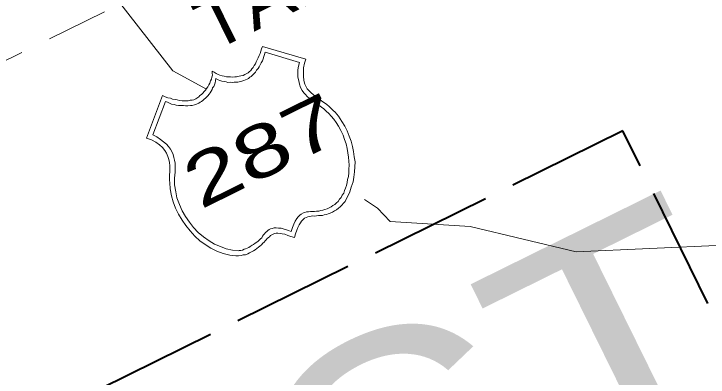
# Model space of a CAD drawing. Extents: x 2356606 to 2371222, y 6973096 to 6982644.
# Drawn here: x 2370773.7 to 2370841.6, y 6980470.1 to 6980505.6 of the extents above; entities that cross this region are included whole.
import ezdxf

# ---------------------------------------------------------------- set-up
doc = ezdxf.new("R2010")
doc.units = 0
doc.header["$LTSCALE"] = 2
doc.linetypes.add('LONG_DASHED', pattern=[7.5, 6, -1.5])
doc.linetypes.add('MEDIUM_DASHED', pattern=[4.5, 3, -1.5])
doc.layers.add('62', color=7, linetype='Continuous', lineweight=13)
doc.layers.add('63', color=7, linetype='Continuous', lineweight=13)

msp = doc.modelspace()

# ---------------------------------------------------------------- linework, layer by layer
at = {"layer": '62', "linetype": 'MEDIUM_DASHED'}
msp.add_line((2371056.951, 6980641.227), (2370654.977, 6980442.841), dxfattribs=at)
at = {"layer": '62'}
for p, q in [((2370789.238, 6980500.02), (2370792.529, 6980498.232)), ((2370809.285, 6980486.6), (2370807.99, 6980487.443))]:
    msp.add_line(p, q, dxfattribs=at)
for points in [[(2370702.875, 6980572.249), (2370710.55, 6980569.261), (2370722.237, 6980561.754), (2370733.315, 6980552.568), (2370741.816, 6980540.43), (2370746.099, 6980533.281), (2370753.777, 6980526.006), (2370764.976, 6980522.023), (2370774.536, 6980517.706), (2370781.469, 6980510.013), (2370789.238, 6980500.02)], [(2370786.658, 6980493.452), (2370788.25, 6980497.601), (2370788.5, 6980497.497), (2370788.753, 6980497.396), (2370789.005, 6980497.345), (2370789.223, 6980497.253), (2370789.465, 6980497.224), (2370789.687, 6980497.18), (2370789.908, 6980497.139), (2370790.149, 6980497.107), (2370790.342, 6980497.077), (2370790.553, 6980497.106), (2370790.751, 6980497.103), (2370790.953, 6980497.153), (2370791.145, 6980497.172), (2370791.306, 6980497.202), (2370791.509, 6980497.302), (2370791.68, 6980497.412), (2370791.791, 6980497.491), (2370791.904, 6980497.622), (2370792.056, 6980497.721), (2370792.196, 6980497.84), (2370792.315, 6980498.001), (2370792.429, 6980498.132), (2370792.55, 6980498.293), (2370792.672, 6980498.453), (2370792.754, 6980498.644), (2370792.865, 6980498.824), (2370792.938, 6980499.034), (2370793.029, 6980499.206), (2370793.058, 6980499.396), (2370793.113, 6980499.597), (2370793.091, 6980499.79), (2370793.11, 6980500), (2370793.292, 6980499.889), (2370793.473, 6980499.775), (2370793.674, 6980499.676), (2370793.854, 6980499.613), (2370794.076, 6980499.522), (2370794.285, 6980499.5), (2370794.489, 6980499.449), (2370794.701, 6980499.429), (2370794.901, 6980499.427), (2370795.093, 6980499.395), (2370795.323, 6980499.435), (2370795.493, 6980499.444), (2370795.737, 6980499.514), (2370795.907, 6980499.521), (2370796.129, 6980499.583), (2370796.29, 6980499.662), (2370796.433, 6980499.73), (2370796.614, 6980499.82), (2370796.703, 6980499.941), (2370796.867, 6980500.072), (2370796.988, 6980500.232), (2370797.099, 6980500.36), (2370797.19, 6980500.532), (2370797.322, 6980500.722), (2370797.413, 6980500.893), (2370797.515, 6980501.094), (2370797.599, 6980501.285), (2370797.709, 6980501.515), (2370797.78, 6980501.727), (2370797.872, 6980501.948), (2370797.932, 6980502.179), (2370798.016, 6980502.421), (2370802.275, 6980501.16), (2370802.142, 6980500.766), (2370802.029, 6980500.335), (2370802.017, 6980499.904), (2370802.045, 6980499.493), (2370802.074, 6980499.079), (2370802.174, 6980498.727), (2370802.302, 6980498.463), (2370802.391, 6980498.282), (2370802.5, 6980498.16), (2370802.652, 6980498.007), (2370802.792, 6980497.877), (2370802.972, 6980497.714), (2370803.171, 6980497.56), (2370803.372, 6980497.411), (2370803.605, 6980497.25), (2370803.843, 6980497.067), (2370804.075, 6980496.903), (2370804.305, 6980496.741), (2370804.536, 6980496.53), (2370804.746, 6980496.357), (2370804.948, 6980496.156), (2370805.136, 6980495.973), (2370805.307, 6980495.78), (2370805.456, 6980495.579), (2370805.776, 6980495.085), (2370806.086, 6980494.61), (2370806.315, 6980494.145), (2370806.494, 6980493.629), (2370806.684, 6980493.144), (2370806.83, 6980492.641), (2370806.929, 6980492.138), (2370807.006, 6980491.624), (2370807.074, 6980491.129), (2370807.07, 6980490.626)], [(2370806.352, 6980489.394), (2370806.423, 6980489.705), (2370806.454, 6980490.045), (2370806.478, 6980490.407), (2370806.491, 6980490.793), (2370806.471, 6980491.185), (2370806.442, 6980491.596), (2370806.383, 6980492.019), (2370806.305, 6980492.434), (2370806.207, 6980492.886), (2370806.05, 6980493.312), (2370805.91, 6980493.745), (2370805.692, 6980494.188), (2370805.461, 6980494.602), (2370805.222, 6980494.985), (2370805.012, 6980495.308), (2370804.751, 6980495.583), (2370804.522, 6980495.845), (2370804.262, 6980496.067), (2370804.02, 6980496.3), (2370803.781, 6980496.483), (2370803.52, 6980496.655), (2370803.258, 6980496.827), (2370803.031, 6980496.99), (2370802.818, 6980497.163), (2370802.607, 6980497.334), (2370802.396, 6980497.508), (2370802.226, 6980497.699), (2370802.067, 6980497.871), (2370801.907, 6980498.093), (2370801.738, 6980498.384), (2370801.649, 6980498.719), (2370801.561, 6980499.052), (2370801.49, 6980499.393), (2370801.464, 6980499.754), (2370801.487, 6980500.119), (2370801.555, 6980500.481), (2370801.63, 6980500.841), (2370798.273, 6980501.845), (2370798.204, 6980501.633), (2370798.149, 6980501.432), (2370798.089, 6980501.201), (2370798.009, 6980501.01), (2370797.907, 6980500.809), (2370797.806, 6980500.609), (2370797.693, 6980500.43), (2370797.583, 6980500.248), (2370797.441, 6980500.078), (2370797.327, 6980499.897), (2370797.176, 6980499.747), (2370797.043, 6980499.606), (2370796.903, 6980499.487), (2370796.772, 6980499.396), (2370796.652, 6980499.286), (2370796.511, 6980499.218), (2370796.368, 6980499.147), (2370796.197, 6980499.088), (2370796.005, 6980499.02), (2370795.855, 6980498.968), (2370795.623, 6980498.931), (2370795.452, 6980498.921), (2370795.262, 6980498.903), (2370795.039, 6980498.893), (2370794.86, 6980498.904), (2370794.637, 6980498.894), (2370794.465, 6980498.936), (2370794.275, 6980498.969), (2370794.052, 6980499.008), (2370793.861, 6980499.09), (2370793.681, 6980499.152), (2370793.47, 6980499.275), (2370793.429, 6980499.051), (2370793.378, 6980498.852), (2370793.316, 6980498.67), (2370793.246, 6980498.51), (2370793.144, 6980498.359), (2370793.092, 6980498.211), (2370792.984, 6980498.028), (2370792.909, 6980497.868), (2370792.79, 6980497.756), (2370792.669, 6980497.596), (2370792.566, 6980497.497), (2370792.435, 6980497.356), (2370792.302, 6980497.267), (2370792.193, 6980497.136), (2370792.041, 6980497.038), (2370791.91, 6980496.946), (2370791.78, 6980496.857), (2370791.577, 6980496.757), (2370791.376, 6980496.709), (2370791.155, 6980496.65), (2370790.961, 6980496.631), (2370790.72, 6980496.61), (2370790.477, 6980496.59), (2370790.289, 6980496.625), (2370790.037, 6980496.624), (2370789.805, 6980496.637), (2370789.582, 6980496.677), (2370789.374, 6980496.748), (2370789.131, 6980496.779), (2370788.911, 6980496.872)], [(2370788.538, 6980497.014), (2370787.282, 6980493.759), (2370787.683, 6980493.557), (2370788.055, 6980493.314), (2370788.346, 6980493.081), (2370788.626, 6980492.867), (2370788.826, 6980492.615), (2370789.027, 6980492.362), (2370789.165, 6980492.131), (2370789.276, 6980491.858), (2370789.344, 6980491.565), (2370789.424, 6980491.304), (2370789.473, 6980491.003), (2370789.472, 6980490.701), (2370789.479, 6980490.428), (2370789.479, 6980490.127), (2370789.446, 6980489.836), (2370789.425, 6980489.523), (2370789.421, 6980488.87), (2370789.527, 6980488.195), (2370789.646, 6980487.6), (2370789.885, 6980486.967), (2370790.164, 6980486.349), (2370790.472, 6980485.773), (2370790.873, 6980485.215), (2370791.273, 6980484.712), (2370791.742, 6980484.217), (2370792.254, 6980483.789), (2370792.796, 6980483.406), (2370793.334, 6980483.07), (2370793.899, 6980482.847), (2370794.48, 6980482.632), (2370795.075, 6980482.498), (2370795.639, 6980482.426), (2370795.75, 6980482.454), (2370795.902, 6980482.453), (2370796.051, 6980482.504), (2370796.213, 6980482.582), (2370796.345, 6980482.623), (2370796.517, 6980482.681), (2370796.678, 6980482.761), (2370796.827, 6980482.861), (2370797, 6980482.972), (2370797.142, 6980483.041), (2370797.304, 6980483.17), (2370797.455, 6980483.271), (2370797.586, 6980483.362), (2370797.718, 6980483.5), (2370797.838, 6980483.61), (2370797.942, 6980483.712), (2370798.02, 6980483.851), (2370798.133, 6980483.98), (2370798.205, 6980484.092), (2370798.314, 6980484.223), (2370798.437, 6980484.331), (2370798.546, 6980484.412), (2370798.678, 6980484.503), (2370798.82, 6980484.572), (2370798.972, 6980484.621), (2370799.172, 6980484.672), (2370799.364, 6980484.69), (2370799.585, 6980484.649), (2370799.836, 6980484.646), (2370800.138, 6980484.544), (2370800.48, 6980484.462), (2370800.832, 6980484.309), (2370800.954, 6980484.721), (2370801.097, 6980485.042), (2370801.23, 6980485.334), (2370801.381, 6980485.583), (2370801.523, 6980485.756), (2370801.674, 6980485.906), (2370801.816, 6980486.026), (2370802.017, 6980486.125), (2370802.169, 6980486.173), (2370802.321, 6980486.226), (2370802.532, 6980486.252), (2370802.722, 6980486.272), (2370802.894, 6980486.282), (2370803.097, 6980486.281), (2370803.307, 6980486.309), (2370803.528, 6980486.317), (2370803.73, 6980486.367), (2370803.941, 6980486.397), (2370804.132, 6980486.466), (2370804.345, 6980486.546), (2370804.536, 6980486.614), (2370804.727, 6980486.735), (2370804.9, 6980486.845), (2370805.09, 6980486.965), (2370805.263, 6980487.125), (2370805.425, 6980487.254), (2370805.566, 6980487.475), (2370805.709, 6980487.646), (2370805.83, 6980487.857), (2370805.971, 6980488.076), (2370806.053, 6980488.318), (2370806.157, 6980488.568), (2370806.239, 6980488.809), (2370806.29, 6980489.112), (2370806.352, 6980489.394)], [(2370788.911, 6980496.872), (2370788.719, 6980496.954), (2370788.538, 6980497.014)], [(2370787.581, 6980493.055), (2370787.17, 6980493.279), (2370786.658, 6980493.452)], [(2370807.07, 6980490.626), (2370807.039, 6980490.134), (2370806.956, 6980489.642), (2370806.892, 6980489.158), (2370806.71, 6980488.667), (2370806.567, 6980488.194), (2370806.351, 6980487.713), (2370806.22, 6980487.472), (2370806.097, 6980487.261), (2370805.936, 6980487.081), (2370805.776, 6980486.9), (2370805.634, 6980486.73), (2370805.452, 6980486.589), (2370805.249, 6980486.441), (2370805.08, 6980486.331), (2370804.866, 6980486.199), (2370804.653, 6980486.121), (2370804.461, 6980486.052), (2370804.29, 6980485.993), (2370804.061, 6980485.954), (2370803.888, 6980485.895), (2370803.695, 6980485.874), (2370803.496, 6980485.876), (2370803.314, 6980485.837), (2370803.123, 6980485.818), (2370802.961, 6980485.839), (2370802.77, 6980485.819), (2370802.641, 6980485.782), (2370802.459, 6980485.74), (2370802.285, 6980485.68), (2370802.147, 6980485.612), (2370802.004, 6980485.492), (2370801.853, 6980485.341), (2370801.743, 6980485.162), (2370801.609, 6980484.971), (2370801.488, 6980484.711), (2370801.366, 6980484.447), (2370801.262, 6980484.098), (2370801.151, 6980483.716), (2370800.788, 6980483.838), (2370800.488, 6980483.94), (2370800.206, 6980484.051), (2370799.944, 6980484.074), (2370799.741, 6980484.124), (2370799.532, 6980484.147), (2370799.36, 6980484.137), (2370799.2, 6980484.105), (2370799.069, 6980484.068), (2370798.928, 6980483.997), (2370798.817, 6980483.919), (2370798.695, 6980483.807), (2370798.605, 6980483.738), (2370798.484, 6980483.63), (2370798.371, 6980483.498), (2370798.271, 6980483.397), (2370798.178, 6980483.278), (2370798.057, 6980483.167), (2370797.926, 6980483.026), (2370797.776, 6980482.878), (2370797.624, 6980482.778), (2370797.463, 6980482.648), (2370797.298, 6980482.517), (2370797.147, 6980482.417), (2370796.948, 6980482.318), (2370796.765, 6980482.228), (2370796.584, 6980482.139), (2370796.35, 6980482.049), (2370796.141, 6980482.02), (2370795.918, 6980481.96), (2370795.673, 6980481.941), (2370795.424, 6980481.941), (2370794.81, 6980482.017), (2370794.177, 6980482.18), (2370793.545, 6980482.394), (2370792.973, 6980482.69), (2370792.401, 6980483.036), (2370791.888, 6980483.41), (2370791.411, 6980483.875), (2370790.939, 6980484.37), (2370790.508, 6980484.887), (2370790.148, 6980485.413), (2370789.809, 6980485.997), (2370789.519, 6980486.583), (2370789.281, 6980487.219), (2370789.113, 6980487.814), (2370788.986, 6980488.478), (2370788.941, 6980489.083), (2370788.92, 6980489.325), (2370788.921, 6980489.576), (2370788.934, 6980489.858), (2370788.945, 6980490.138), (2370788.946, 6980490.442), (2370788.95, 6980490.743), (2370788.918, 6980491.055), (2370788.85, 6980491.348), (2370788.773, 6980491.661), (2370788.622, 6980491.962), (2370788.463, 6980492.234), (2370788.223, 6980492.518), (2370787.94, 6980492.78), (2370787.581, 6980493.055)], [(2370809.285, 6980486.6), (2370810.526, 6980485.306), (2370818.332, 6980484.791), (2370828.717, 6980482.314), (2370843.121, 6980482.975), (2370855.891, 6980481.246), (2370863.629, 6980480.974)]]:
    msp.add_lwpolyline(points, dxfattribs=at)
at = {"layer": '62', "linetype": 'LONG_DASHED', "lineweight": 40}
msp.add_lwpolyline([(2370677.388, 6980417.215), (2370705.629, 6980359.988), (2370861.529, 6980436.93), (2370833.286, 6980494.155), (2370677.105, 6980417.075)], dxfattribs=at)
at = {"layer": '63', "linetype": 'MEDIUM_DASHED'}
msp.add_line((2371056.951, 6980641.227), (2370654.977, 6980442.841), dxfattribs=at)
at = {"layer": '63'}
for p, q in [((2370789.238, 6980500.02), (2370792.529, 6980498.232)), ((2370809.285, 6980486.6), (2370807.99, 6980487.443))]:
    msp.add_line(p, q, dxfattribs=at)
for points in [[(2370702.875, 6980572.249), (2370710.55, 6980569.261), (2370722.237, 6980561.754), (2370733.315, 6980552.568), (2370741.816, 6980540.43), (2370746.099, 6980533.281), (2370753.777, 6980526.006), (2370764.976, 6980522.023), (2370774.536, 6980517.706), (2370781.469, 6980510.013), (2370789.238, 6980500.02)], [(2370786.658, 6980493.452), (2370788.25, 6980497.601), (2370788.5, 6980497.497), (2370788.753, 6980497.396), (2370789.005, 6980497.345), (2370789.223, 6980497.253), (2370789.465, 6980497.224), (2370789.687, 6980497.18), (2370789.908, 6980497.139), (2370790.149, 6980497.107), (2370790.342, 6980497.077), (2370790.553, 6980497.106), (2370790.751, 6980497.103), (2370790.953, 6980497.153), (2370791.145, 6980497.172), (2370791.306, 6980497.202), (2370791.509, 6980497.302), (2370791.68, 6980497.412), (2370791.791, 6980497.491), (2370791.904, 6980497.622), (2370792.056, 6980497.721), (2370792.196, 6980497.84), (2370792.315, 6980498.001), (2370792.429, 6980498.132), (2370792.55, 6980498.293), (2370792.672, 6980498.453), (2370792.754, 6980498.644), (2370792.865, 6980498.824), (2370792.938, 6980499.034), (2370793.029, 6980499.206), (2370793.058, 6980499.396), (2370793.113, 6980499.597), (2370793.091, 6980499.79), (2370793.11, 6980500), (2370793.292, 6980499.889), (2370793.473, 6980499.775), (2370793.674, 6980499.676), (2370793.854, 6980499.613), (2370794.076, 6980499.522), (2370794.285, 6980499.5), (2370794.489, 6980499.449), (2370794.701, 6980499.429), (2370794.901, 6980499.427), (2370795.093, 6980499.395), (2370795.323, 6980499.435), (2370795.493, 6980499.444), (2370795.737, 6980499.514), (2370795.907, 6980499.521), (2370796.129, 6980499.583), (2370796.29, 6980499.662), (2370796.433, 6980499.73), (2370796.614, 6980499.82), (2370796.703, 6980499.941), (2370796.867, 6980500.072), (2370796.988, 6980500.232), (2370797.099, 6980500.36), (2370797.19, 6980500.532), (2370797.322, 6980500.722), (2370797.413, 6980500.893), (2370797.515, 6980501.094), (2370797.599, 6980501.285), (2370797.709, 6980501.515), (2370797.78, 6980501.727), (2370797.872, 6980501.948), (2370797.932, 6980502.179), (2370798.016, 6980502.421), (2370802.275, 6980501.16), (2370802.142, 6980500.766), (2370802.029, 6980500.335), (2370802.017, 6980499.904), (2370802.045, 6980499.493), (2370802.074, 6980499.079), (2370802.174, 6980498.727), (2370802.302, 6980498.463), (2370802.391, 6980498.282), (2370802.5, 6980498.16), (2370802.652, 6980498.007), (2370802.792, 6980497.877), (2370802.972, 6980497.714), (2370803.171, 6980497.56), (2370803.372, 6980497.411), (2370803.605, 6980497.25), (2370803.843, 6980497.067), (2370804.075, 6980496.903), (2370804.305, 6980496.741), (2370804.536, 6980496.53), (2370804.746, 6980496.357), (2370804.948, 6980496.156), (2370805.136, 6980495.973), (2370805.307, 6980495.78), (2370805.456, 6980495.579), (2370805.776, 6980495.085), (2370806.086, 6980494.61), (2370806.315, 6980494.145), (2370806.494, 6980493.629), (2370806.684, 6980493.144), (2370806.83, 6980492.641), (2370806.929, 6980492.138), (2370807.006, 6980491.624), (2370807.074, 6980491.129), (2370807.07, 6980490.626)], [(2370806.352, 6980489.394), (2370806.423, 6980489.705), (2370806.454, 6980490.045), (2370806.478, 6980490.407), (2370806.491, 6980490.793), (2370806.471, 6980491.185), (2370806.442, 6980491.596), (2370806.383, 6980492.019), (2370806.305, 6980492.434), (2370806.207, 6980492.886), (2370806.05, 6980493.312), (2370805.91, 6980493.745), (2370805.692, 6980494.188), (2370805.461, 6980494.602), (2370805.222, 6980494.985), (2370805.012, 6980495.308), (2370804.751, 6980495.583), (2370804.522, 6980495.845), (2370804.262, 6980496.067), (2370804.02, 6980496.3), (2370803.781, 6980496.483), (2370803.52, 6980496.655), (2370803.258, 6980496.827), (2370803.031, 6980496.99), (2370802.818, 6980497.163), (2370802.607, 6980497.334), (2370802.396, 6980497.508), (2370802.226, 6980497.699), (2370802.067, 6980497.871), (2370801.907, 6980498.093), (2370801.738, 6980498.384), (2370801.649, 6980498.719), (2370801.561, 6980499.052), (2370801.49, 6980499.393), (2370801.464, 6980499.754), (2370801.487, 6980500.119), (2370801.555, 6980500.481), (2370801.63, 6980500.841), (2370798.273, 6980501.845), (2370798.204, 6980501.633), (2370798.149, 6980501.432), (2370798.089, 6980501.201), (2370798.009, 6980501.01), (2370797.907, 6980500.809), (2370797.806, 6980500.609), (2370797.693, 6980500.43), (2370797.583, 6980500.248), (2370797.441, 6980500.078), (2370797.327, 6980499.897), (2370797.176, 6980499.747), (2370797.043, 6980499.606), (2370796.903, 6980499.487), (2370796.772, 6980499.396), (2370796.652, 6980499.286), (2370796.511, 6980499.218), (2370796.368, 6980499.147), (2370796.197, 6980499.088), (2370796.005, 6980499.02), (2370795.855, 6980498.968), (2370795.623, 6980498.931), (2370795.452, 6980498.921), (2370795.262, 6980498.903), (2370795.039, 6980498.893), (2370794.86, 6980498.904), (2370794.637, 6980498.894), (2370794.465, 6980498.936), (2370794.275, 6980498.969), (2370794.052, 6980499.008), (2370793.861, 6980499.09), (2370793.681, 6980499.152), (2370793.47, 6980499.275), (2370793.429, 6980499.051), (2370793.378, 6980498.852), (2370793.316, 6980498.67), (2370793.246, 6980498.51), (2370793.144, 6980498.359), (2370793.092, 6980498.211), (2370792.984, 6980498.028), (2370792.909, 6980497.868), (2370792.79, 6980497.756), (2370792.669, 6980497.596), (2370792.566, 6980497.497), (2370792.435, 6980497.356), (2370792.302, 6980497.267), (2370792.193, 6980497.136), (2370792.041, 6980497.038), (2370791.91, 6980496.946), (2370791.78, 6980496.857), (2370791.577, 6980496.757), (2370791.376, 6980496.709), (2370791.155, 6980496.65), (2370790.961, 6980496.631), (2370790.72, 6980496.61), (2370790.477, 6980496.59), (2370790.289, 6980496.625), (2370790.037, 6980496.624), (2370789.805, 6980496.637), (2370789.582, 6980496.677), (2370789.374, 6980496.748), (2370789.131, 6980496.779), (2370788.911, 6980496.872)], [(2370788.538, 6980497.014), (2370787.282, 6980493.759), (2370787.683, 6980493.557), (2370788.055, 6980493.314), (2370788.346, 6980493.081), (2370788.626, 6980492.867), (2370788.826, 6980492.615), (2370789.027, 6980492.362), (2370789.165, 6980492.131), (2370789.276, 6980491.858), (2370789.344, 6980491.565), (2370789.424, 6980491.304), (2370789.473, 6980491.003), (2370789.472, 6980490.701), (2370789.479, 6980490.428), (2370789.479, 6980490.127), (2370789.446, 6980489.836), (2370789.425, 6980489.523), (2370789.421, 6980488.87), (2370789.527, 6980488.195), (2370789.646, 6980487.6), (2370789.885, 6980486.967), (2370790.164, 6980486.349), (2370790.472, 6980485.773), (2370790.873, 6980485.215), (2370791.273, 6980484.712), (2370791.742, 6980484.217), (2370792.254, 6980483.789), (2370792.796, 6980483.406), (2370793.334, 6980483.07), (2370793.899, 6980482.847), (2370794.48, 6980482.632), (2370795.075, 6980482.498), (2370795.639, 6980482.426), (2370795.75, 6980482.454), (2370795.902, 6980482.453), (2370796.051, 6980482.504), (2370796.213, 6980482.582), (2370796.345, 6980482.623), (2370796.517, 6980482.681), (2370796.678, 6980482.761), (2370796.827, 6980482.861), (2370797, 6980482.972), (2370797.142, 6980483.041), (2370797.304, 6980483.17), (2370797.455, 6980483.271), (2370797.586, 6980483.362), (2370797.718, 6980483.5), (2370797.838, 6980483.61), (2370797.942, 6980483.712), (2370798.02, 6980483.851), (2370798.133, 6980483.98), (2370798.205, 6980484.092), (2370798.314, 6980484.223), (2370798.437, 6980484.331), (2370798.546, 6980484.412), (2370798.678, 6980484.503), (2370798.82, 6980484.572), (2370798.972, 6980484.621), (2370799.172, 6980484.672), (2370799.364, 6980484.69), (2370799.585, 6980484.649), (2370799.836, 6980484.646), (2370800.138, 6980484.544), (2370800.48, 6980484.462), (2370800.832, 6980484.309), (2370800.954, 6980484.721), (2370801.097, 6980485.042), (2370801.23, 6980485.334), (2370801.381, 6980485.583), (2370801.523, 6980485.756), (2370801.674, 6980485.906), (2370801.816, 6980486.026), (2370802.017, 6980486.125), (2370802.169, 6980486.173), (2370802.321, 6980486.226), (2370802.532, 6980486.252), (2370802.722, 6980486.272), (2370802.894, 6980486.282), (2370803.097, 6980486.281), (2370803.307, 6980486.309), (2370803.528, 6980486.317), (2370803.73, 6980486.367), (2370803.941, 6980486.397), (2370804.132, 6980486.466), (2370804.345, 6980486.546), (2370804.536, 6980486.614), (2370804.727, 6980486.735), (2370804.9, 6980486.845), (2370805.09, 6980486.965), (2370805.263, 6980487.125), (2370805.425, 6980487.254), (2370805.566, 6980487.475), (2370805.709, 6980487.646), (2370805.83, 6980487.857), (2370805.971, 6980488.076), (2370806.053, 6980488.318), (2370806.157, 6980488.568), (2370806.239, 6980488.809), (2370806.29, 6980489.112), (2370806.352, 6980489.394)], [(2370788.911, 6980496.872), (2370788.719, 6980496.954), (2370788.538, 6980497.014)], [(2370787.581, 6980493.055), (2370787.17, 6980493.279), (2370786.658, 6980493.452)], [(2370807.07, 6980490.626), (2370807.039, 6980490.134), (2370806.956, 6980489.642), (2370806.892, 6980489.158), (2370806.71, 6980488.667), (2370806.567, 6980488.194), (2370806.351, 6980487.713), (2370806.22, 6980487.472), (2370806.097, 6980487.261), (2370805.936, 6980487.081), (2370805.776, 6980486.9), (2370805.634, 6980486.73), (2370805.452, 6980486.589), (2370805.249, 6980486.441), (2370805.08, 6980486.331), (2370804.866, 6980486.199), (2370804.653, 6980486.121), (2370804.461, 6980486.052), (2370804.29, 6980485.993), (2370804.061, 6980485.954), (2370803.888, 6980485.895), (2370803.695, 6980485.874), (2370803.496, 6980485.876), (2370803.314, 6980485.837), (2370803.123, 6980485.818), (2370802.961, 6980485.839), (2370802.77, 6980485.819), (2370802.641, 6980485.782), (2370802.459, 6980485.74), (2370802.285, 6980485.68), (2370802.147, 6980485.612), (2370802.004, 6980485.492), (2370801.853, 6980485.341), (2370801.743, 6980485.162), (2370801.609, 6980484.971), (2370801.488, 6980484.711), (2370801.366, 6980484.447), (2370801.262, 6980484.098), (2370801.151, 6980483.716), (2370800.788, 6980483.838), (2370800.488, 6980483.94), (2370800.206, 6980484.051), (2370799.944, 6980484.074), (2370799.741, 6980484.124), (2370799.532, 6980484.147), (2370799.36, 6980484.137), (2370799.2, 6980484.105), (2370799.069, 6980484.068), (2370798.928, 6980483.997), (2370798.817, 6980483.919), (2370798.695, 6980483.807), (2370798.605, 6980483.738), (2370798.484, 6980483.63), (2370798.371, 6980483.498), (2370798.271, 6980483.397), (2370798.178, 6980483.278), (2370798.057, 6980483.167), (2370797.926, 6980483.026), (2370797.776, 6980482.878), (2370797.624, 6980482.778), (2370797.463, 6980482.648), (2370797.298, 6980482.517), (2370797.147, 6980482.417), (2370796.948, 6980482.318), (2370796.765, 6980482.228), (2370796.584, 6980482.139), (2370796.35, 6980482.049), (2370796.141, 6980482.02), (2370795.918, 6980481.96), (2370795.673, 6980481.941), (2370795.424, 6980481.941), (2370794.81, 6980482.017), (2370794.177, 6980482.18), (2370793.545, 6980482.394), (2370792.973, 6980482.69), (2370792.401, 6980483.036), (2370791.888, 6980483.41), (2370791.411, 6980483.875), (2370790.939, 6980484.37), (2370790.508, 6980484.887), (2370790.148, 6980485.413), (2370789.809, 6980485.997), (2370789.519, 6980486.583), (2370789.281, 6980487.219), (2370789.113, 6980487.814), (2370788.986, 6980488.478), (2370788.941, 6980489.083), (2370788.92, 6980489.325), (2370788.921, 6980489.576), (2370788.934, 6980489.858), (2370788.945, 6980490.138), (2370788.946, 6980490.442), (2370788.95, 6980490.743), (2370788.918, 6980491.055), (2370788.85, 6980491.348), (2370788.773, 6980491.661), (2370788.622, 6980491.962), (2370788.463, 6980492.234), (2370788.223, 6980492.518), (2370787.94, 6980492.78), (2370787.581, 6980493.055)], [(2370809.285, 6980486.6), (2370810.526, 6980485.306), (2370818.332, 6980484.791), (2370828.717, 6980482.314), (2370843.121, 6980482.975), (2370855.891, 6980481.246), (2370863.629, 6980480.974)]]:
    msp.add_lwpolyline(points, dxfattribs=at)
at = {"layer": '63', "linetype": 'LONG_DASHED', "lineweight": 40}
msp.add_lwpolyline([(2370677.388, 6980417.215), (2370705.629, 6980359.988), (2370861.529, 6980436.93), (2370833.286, 6980494.155), (2370677.105, 6980417.075)], dxfattribs=at)

# ---------------------------------------------------------------- texts
at = {"layer": '62'}
for s, height, width, p in [('TARRANT', 5.099, 1.1, (2370793.071, 6980501.81)), ('287', 5.099, 1.4, (2370791.955, 6980486.431)), ('PROJECT', 23.83, 1.15, (2370694.907, 6980391.635))]:
    msp.add_text(s, height=height, rotation=26.268, dxfattribs=dict(at, width=width)).set_placement(p)
at = {"layer": '63'}
for s, height, width, p in [('TARRANT', 5.099, 1.1, (2370793.071, 6980501.81)), ('287', 5.099, 1.4, (2370791.955, 6980486.431)), ('PROJECT', 23.83, 1.15, (2370694.907, 6980391.635))]:
    msp.add_text(s, height=height, rotation=26.268, dxfattribs=dict(at, width=width)).set_placement(p)

doc.saveas('drawing.dxf')
